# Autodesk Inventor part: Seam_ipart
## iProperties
Shininess: 69.0
Length Units: 11269
Angle Units: 11279
Time Units: 11290
Mass Units: 11283
Length Display Precision: 3
Angle Display Precision: 2
Created: 2001-05
Part Number: Seam_ipart
Material: Standard
Document SubType Name: Modellieren
Designer: dl
Density: 1 g/cm^3
Density: 0.0
Volumn: 0.0
Area: 0.0
PropertySet Name: Model Information
Control State: 0
Master: False
Checked Out: False
Author: dl
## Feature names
1. Abgeleiteter Körper1 [Tagging]
